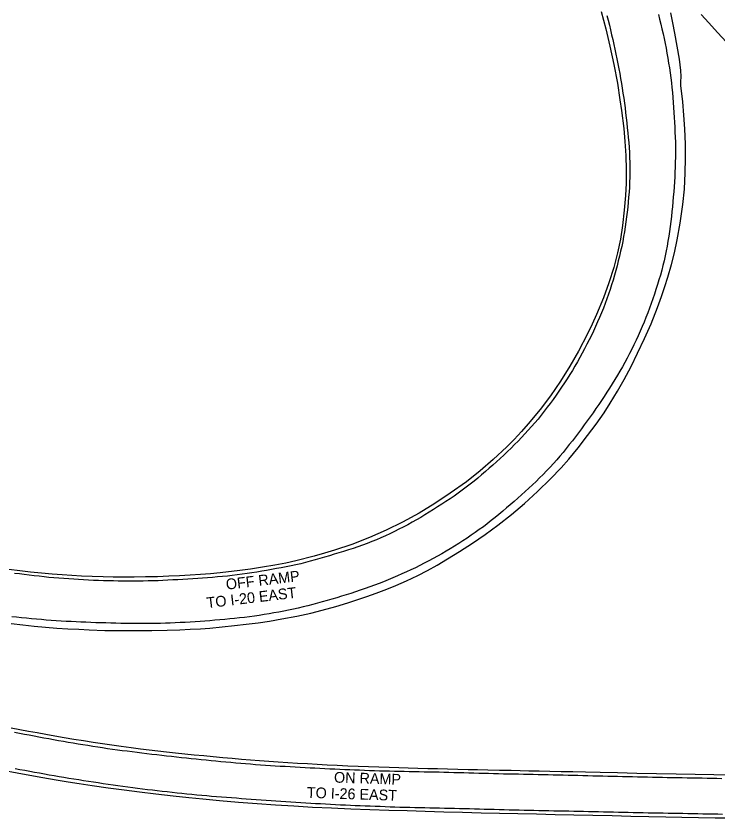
# Model space of a CAD drawing. Extents: x 1948091 to 1975253, y 787267 to 823306.
# Drawn here: x 1966364.3 to 1966717.4, y 800935.2 to 801338.4 of the extents above; entities that cross this region are included whole.
import ezdxf

# ---------------------------------------------------------------- set-up
doc = ezdxf.new("R2010")
doc.units = 0
for name, color, linetype in [('RD_EX_Pavement_Markings', 7, 'Continuous'), ('RD_EX_Road', 7, 'Continuous'), ('RD_TX_RoadID', 7, 'Continuous')]:
    doc.layers.add(name, color=color, linetype=linetype)

msp = doc.modelspace()

# ---------------------------------------------------------------- linework, layer by layer
at = {"layer": 'RD_EX_Pavement_Markings'}
for points in [[(1966687.48, 801339.26), (1966688.08, 801336.83), (1966688.68, 801334.41), (1966689.25, 801331.97), (1966689.82, 801329.54), (1966690.35, 801327.1), (1966690.85, 801324.65), (1966691.34, 801322.2), (1966691.77, 801319.73), (1966692.21, 801317.27), (1966692.61, 801314.8), (1966692.99, 801312.33), (1966693.35, 801309.86), (1966693.67, 801307.38), (1966693.97, 801304.9), (1966694.22, 801302.41), (1966694.47, 801299.93), (1966694.68, 801297.44), (1966694.9, 801294.95), (1966695.07, 801292.45), (1966695.25, 801289.96), (1966695.4, 801287.46), (1966695.55, 801284.97), (1966695.69, 801282.47), (1966695.8, 801279.98), (1966695.91, 801277.48), (1966695.98, 801274.98), (1966696, 801272.48), (1966696.01, 801269.98), (1966695.99, 801267.48), (1966695.95, 801264.98), (1966695.87, 801262.49), (1966695.8, 801259.99), (1966695.67, 801257.49), (1966695.54, 801255), (1966695.36, 801252.5), (1966695.16, 801250.01), (1966694.96, 801247.52), (1966694.73, 801245.03), (1966694.51, 801242.54), (1966694.26, 801240.06), (1966694, 801237.57), (1966693.73, 801235.09), (1966693.38, 801232.61), (1966693.03, 801230.14), (1966692.64, 801227.67), (1966692.24, 801225.2), (1966691.81, 801222.74), (1966691.37, 801220.28), (1966690.87, 801217.83), (1966690.33, 801215.39), (1966689.73, 801212.96), (1966689.1, 801210.55), (1966688.43, 801208.14), (1966687.71, 801205.75), (1966686.99, 801203.35), (1966686.24, 801200.97), (1966685.49, 801198.59), (1966684.68, 801196.22), (1966683.84, 801193.87), (1966682.96, 801191.53), (1966682.07, 801189.2), (1966681.16, 801186.87), (1966680.24, 801184.55), (1966679.26, 801182.25), (1966678.27, 801179.95), (1966677.26, 801177.67), (1966676.23, 801175.39), (1966675.15, 801173.14), (1966674.07, 801170.89), (1966672.93, 801168.67), (1966671.78, 801166.45), (1966670.58, 801164.25), (1966669.36, 801162.08), (1966668.12, 801159.91), (1966666.84, 801157.76), (1966665.56, 801155.62), (1966664.27, 801153.48), (1966662.93, 801151.37), (1966661.58, 801149.27), (1966660.2, 801147.18), (1966658.81, 801145.11), (1966657.43, 801143.03), (1966656.01, 801140.98), (1966654.58, 801138.93), (1966653.14, 801136.88), (1966651.67, 801134.86), (1966650.19, 801132.85), (1966648.71, 801130.84), (1966647.2, 801128.85), (1966645.69, 801126.86), (1966644.18, 801124.87), (1966642.64, 801122.9), (1966641.11, 801120.93), (1966639.53, 801119), (1966637.92, 801117.09), (1966636.28, 801115.2), (1966634.62, 801113.34), (1966632.94, 801111.49), (1966631.22, 801109.68), (1966629.48, 801107.89), (1966627.71, 801106.12), (1966625.94, 801104.36), (1966624.11, 801102.66), (1966622.28, 801100.96), (1966620.44, 801099.27), (1966618.58, 801097.6), (1966616.7, 801095.96), (1966614.82, 801094.31), (1966612.93, 801092.68), (1966611.03, 801091.06), (1966609.14, 801089.43), (1966607.22, 801087.83), (1966605.29, 801086.24), (1966603.35, 801084.67), (1966601.37, 801083.14), (1966599.4, 801081.62), (1966597.37, 801080.16), (1966595.32, 801078.72), (1966593.26, 801077.31), (1966591.2, 801075.9), (1966589.14, 801074.5), (1966587.02, 801073.17), (1966584.91, 801071.84), (1966582.77, 801070.54), (1966580.63, 801069.26), (1966578.48, 801067.99), (1966576.3, 801066.77), (1966574.12, 801065.55), (1966571.91, 801064.39), (1966569.7, 801063.24), (1966567.46, 801062.12), (1966565.22, 801061.01), (1966562.99, 801059.91), (1966560.71, 801058.88), (1966558.44, 801057.84), (1966556.15, 801056.84), (1966553.85, 801055.87), (1966551.55, 801054.9), (1966549.23, 801053.97), (1966546.91, 801053.05), (1966544.57, 801052.16), (1966542.22, 801051.32), (1966539.87, 801050.47), (1966537.51, 801049.66), (1966535.15, 801048.86), (1966532.78, 801048.06), (1966530.39, 801047.32), (1966528, 801046.61), (1966525.61, 801045.9), (1966523.21, 801045.21), (1966520.8, 801044.54), (1966518.39, 801043.87), (1966515.98, 801043.21), (1966513.57, 801042.56), (1966511.16, 801041.91), (1966508.74, 801041.29), (1966506.31, 801040.73), (1966503.87, 801040.18), (1966501.43, 801039.67), (1966498.98, 801039.19), (1966496.53, 801038.72), (1966494.07, 801038.27), (1966491.61, 801037.82), (1966489.15, 801037.43), (1966486.68, 801037.05), (1966484.21, 801036.69), (1966481.73, 801036.36), (1966479.26, 801036.03), (1966476.77, 801035.75), (1966474.29, 801035.48), (1966471.81, 801035.21), (1966469.32, 801034.99), (1966466.83, 801034.77), (1966464.35, 801034.54), (1966461.86, 801034.36), (1966459.36, 801034.18), (1966456.87, 801034.01), (1966454.38, 801033.83), (1966451.89, 801033.68), (1966449.4, 801033.53), (1966446.9, 801033.39), (1966444.41, 801033.28), (1966441.91, 801033.18), (1966439.42, 801033.08), (1966436.92, 801033.02), (1966434.43, 801032.98), (1966431.93, 801032.93), (1966429.43, 801032.9), (1966426.93, 801032.9), (1966424.44, 801032.9), (1966421.94, 801032.92), (1966419.44, 801032.97), (1966416.95, 801033.01), (1966414.45, 801033.07), (1966411.95, 801033.13), (1966409.46, 801033.2), (1966406.96, 801033.26), (1966404.47, 801033.34), (1966401.97, 801033.44), (1966399.48, 801033.54), (1966396.98, 801033.65), (1966394.48, 801033.75), (1966391.99, 801033.89), (1966389.5, 801034.03), (1966387.01, 801034.16), (1966384.51, 801034.3), (1966382.02, 801034.48), (1966379.53, 801034.69), (1966377.04, 801034.89), (1966374.55, 801035.09), (1966372.07, 801035.32), (1966369.58, 801035.55), (1966367.09, 801035.81), (1966364.61, 801036.07), (1966362.13, 801036.33)], [(1966661.44, 801338.73), (1966662.11, 801336.32), (1966662.77, 801333.91), (1966663.35, 801331.48), (1966663.94, 801329.05), (1966664.52, 801326.62), (1966665.05, 801324.18), (1966665.57, 801321.73), (1966666.08, 801319.29), (1966666.59, 801316.84), (1966667.06, 801314.38), (1966667.52, 801311.93), (1966667.99, 801309.47), (1966668.45, 801307.02), (1966668.85, 801304.55), (1966669.24, 801302.08), (1966669.63, 801299.61), (1966670.02, 801297.14), (1966670.35, 801294.67), (1966670.68, 801292.19), (1966670.98, 801289.71), (1966671.25, 801287.22), (1966671.51, 801284.74), (1966671.78, 801282.25), (1966672.04, 801279.77), (1966672.28, 801277.28), (1966672.5, 801274.79), (1966672.7, 801272.3), (1966672.85, 801269.8), (1966672.97, 801267.31), (1966673.02, 801264.81), (1966673.07, 801262.31), (1966673.05, 801259.81), (1966673.04, 801257.31), (1966672.95, 801254.81), (1966672.84, 801252.32), (1966672.69, 801249.82), (1966672.49, 801247.33), (1966672.3, 801244.84), (1966672.06, 801242.35), (1966671.79, 801239.87), (1966671.46, 801237.39), (1966671.12, 801234.91), (1966670.74, 801232.44), (1966670.33, 801229.98), (1966669.91, 801227.52), (1966669.49, 801225.05), (1966668.98, 801222.61), (1966668.46, 801220.16), (1966667.9, 801217.73), (1966667.29, 801215.3), (1966666.68, 801212.88), (1966666.03, 801210.47), (1966665.34, 801208.07), (1966664.64, 801205.67), (1966663.89, 801203.29), (1966663.13, 801200.91), (1966662.37, 801198.53), (1966661.52, 801196.17), (1966660.67, 801193.83), (1966659.77, 801191.5), (1966658.85, 801189.18), (1966657.88, 801186.88), (1966656.89, 801184.58), (1966655.87, 801182.3), (1966654.82, 801180.03), (1966653.72, 801177.79), (1966652.58, 801175.57), (1966651.43, 801173.35), (1966650.26, 801171.14), (1966649.09, 801168.94), (1966647.92, 801166.73), (1966646.69, 801164.55), (1966645.45, 801162.39), (1966644.16, 801160.25), (1966642.84, 801158.13), (1966641.51, 801156.02), (1966640.15, 801153.92), (1966638.79, 801151.83), (1966637.4, 801149.75), (1966635.98, 801147.7), (1966634.56, 801145.65), (1966633.05, 801143.65), (1966631.55, 801141.66), (1966630.04, 801139.67), (1966628.49, 801137.71), (1966626.91, 801135.77), (1966625.31, 801133.86), (1966623.65, 801131.99), (1966621.98, 801130.13), (1966620.27, 801128.31), (1966618.56, 801126.49), (1966616.83, 801124.69), (1966615.09, 801122.9), (1966613.33, 801121.13), (1966611.53, 801119.4), (1966609.73, 801117.67), (1966607.89, 801115.99), (1966606.04, 801114.3), (1966604.18, 801112.64), (1966602.3, 801111), (1966600.42, 801109.36), (1966598.54, 801107.71), (1966596.67, 801106.05), (1966594.72, 801104.5), (1966592.75, 801102.96), (1966590.77, 801101.45), (1966588.76, 801099.96), (1966586.75, 801098.48), (1966584.7, 801097.05), (1966582.64, 801095.64), (1966580.58, 801094.23), (1966578.48, 801092.88), (1966576.38, 801091.53), (1966574.27, 801090.19), (1966572.14, 801088.89), (1966570.01, 801087.59), (1966567.87, 801086.29), (1966565.69, 801085.07), (1966563.52, 801083.84), (1966561.33, 801082.64), (1966559.12, 801081.46), (1966556.91, 801080.3), (1966554.68, 801079.18), (1966552.43, 801078.09), (1966550.15, 801077.08), (1966547.87, 801076.06), (1966545.57, 801075.08), (1966543.27, 801074.1), (1966540.95, 801073.19), (1966538.61, 801072.32), (1966536.25, 801071.48), (1966533.88, 801070.7), (1966531.5, 801069.94), (1966529.12, 801069.21), (1966526.73, 801068.48), (1966524.34, 801067.75), (1966521.95, 801067.03), (1966519.56, 801066.31), (1966517.16, 801065.62), (1966514.76, 801064.94), (1966512.35, 801064.26), (1966509.94, 801063.64), (1966507.51, 801063.03), (1966505.09, 801062.45), (1966502.64, 801061.94), (1966500.2, 801061.44), (1966497.74, 801060.98), (1966495.29, 801060.52), (1966492.84, 801060.06), (1966490.38, 801059.6), (1966487.92, 801059.2), (1966485.45, 801058.81), (1966482.99, 801058.42), (1966480.52, 801058.06), (1966478.04, 801057.73), (1966475.57, 801057.41), (1966473.09, 801057.08), (1966470.61, 801056.78), (1966468.13, 801056.55), (1966465.64, 801056.33), (1966463.16, 801056.1), (1966460.67, 801055.91), (1966458.18, 801055.73), (1966455.69, 801055.56), (1966453.2, 801055.39), (1966450.71, 801055.21), (1966448.21, 801055.08), (1966445.72, 801054.95), (1966443.23, 801054.82), (1966440.73, 801054.68), (1966438.24, 801054.56), (1966435.74, 801054.48), (1966433.25, 801054.4), (1966430.75, 801054.32), (1966428.26, 801054.24), (1966425.76, 801054.19), (1966423.26, 801054.21), (1966420.76, 801054.24), (1966418.27, 801054.26), (1966415.77, 801054.28), (1966413.27, 801054.34), (1966410.78, 801054.41), (1966408.28, 801054.47), (1966405.79, 801054.54), (1966403.29, 801054.64), (1966400.8, 801054.77), (1966398.3, 801054.89), (1966395.81, 801055.02), (1966393.32, 801055.18), (1966390.83, 801055.36), (1966388.34, 801055.54), (1966385.85, 801055.72), (1966383.35, 801055.9), (1966380.87, 801056.16), (1966378.39, 801056.42), (1966375.9, 801056.68), (1966373.42, 801056.95), (1966370.94, 801057.24), (1966368.46, 801057.54), (1966365.98, 801057.84), (1966363.5, 801058.14)], [(1966363.59, 800978.29), (1966366.05, 800977.82), (1966368.5, 800977.35), (1966370.95, 800976.89), (1966373.41, 800976.42), (1966375.86, 800975.97), (1966378.32, 800975.52), (1966380.77, 800975.07), (1966383.23, 800974.62), (1966385.68, 800974.17), (1966388.14, 800973.74), (1966390.61, 800973.33), (1966393.07, 800972.92), (1966395.53, 800972.5), (1966397.99, 800972.09), (1966400.46, 800971.69), (1966402.92, 800971.3), (1966405.39, 800970.91), (1966407.85, 800970.52), (1966410.33, 800970.17), (1966412.8, 800969.82), (1966415.27, 800969.48), (1966417.75, 800969.15), (1966420.22, 800968.83), (1966422.7, 800968.5), (1966425.17, 800968.18), (1966427.65, 800967.88), (1966430.13, 800967.6), (1966432.62, 800967.32), (1966435.1, 800967.03), (1966437.58, 800966.75), (1966440.06, 800966.47), (1966442.54, 800966.19), (1966445.02, 800965.92), (1966447.5, 800965.64), (1966449.98, 800965.37), (1966452.47, 800965.09), (1966454.95, 800964.85), (1966457.44, 800964.6), (1966459.92, 800964.35), (1966462.4, 800964.11), (1966464.89, 800963.86), (1966467.38, 800963.62), (1966469.86, 800963.39), (1966472.35, 800963.16), (1966474.83, 800962.93), (1966477.32, 800962.72), (1966479.81, 800962.52), (1966482.3, 800962.32), (1966484.79, 800962.12), (1966487.28, 800961.93), (1966489.77, 800961.77), (1966492.26, 800961.61), (1966494.75, 800961.44), (1966497.25, 800961.28), (1966499.74, 800961.12), (1966502.23, 800960.98), (1966504.72, 800960.85), (1966507.22, 800960.71), (1966509.71, 800960.57), (1966512.2, 800960.43), (1966514.7, 800960.29), (1966517.19, 800960.17), (1966519.68, 800960.05), (1966522.18, 800959.94), (1966524.67, 800959.82), (1966527.17, 800959.7), (1966529.66, 800959.58), (1966532.16, 800959.47), (1966534.65, 800959.38), (1966537.15, 800959.28), (1966539.64, 800959.19), (1966542.14, 800959.1), (1966544.63, 800959), (1966547.13, 800958.93), (1966549.63, 800958.87), (1966552.12, 800958.81), (1966554.62, 800958.75), (1966557.12, 800958.69), (1966559.61, 800958.63), (1966562.11, 800958.58), (1966564.6, 800958.53), (1966567.1, 800958.48), (1966569.6, 800958.42), (1966572.1, 800958.37), (1966574.59, 800958.32), (1966577.09, 800958.27), (1966579.59, 800958.22), (1966582.08, 800958.17), (1966584.58, 800958.1), (1966587.07, 800958.03), (1966589.57, 800957.96), (1966592.07, 800957.89), (1966594.56, 800957.83), (1966597.06, 800957.76), (1966599.56, 800957.69), (1966602.05, 800957.62), (1966604.55, 800957.55), (1966607.05, 800957.49), (1966609.54, 800957.43), (1966612.04, 800957.38), (1966614.53, 800957.33), (1966617.03, 800957.27), (1966619.53, 800957.22), (1966622.02, 800957.16), (1966624.52, 800957.11), (1966627.02, 800957.05), (1966629.51, 800957), (1966632.01, 800956.94), (1966634.51, 800956.89), (1966637, 800956.83), (1966639.5, 800956.77), (1966642, 800956.71), (1966644.49, 800956.65), (1966646.99, 800956.6), (1966649.49, 800956.54), (1966651.98, 800956.48), (1966654.48, 800956.42), (1966656.98, 800956.36), (1966659.47, 800956.31), (1966661.97, 800956.25), (1966664.47, 800956.19), (1966666.96, 800956.13), (1966669.46, 800956.07), (1966671.96, 800956.01), (1966674.45, 800955.95), (1966676.95, 800955.89), (1966679.45, 800955.83), (1966681.94, 800955.77), (1966684.44, 800955.71), (1966686.94, 800955.66), (1966689.44, 800955.62), (1966691.93, 800955.57), (1966694.43, 800955.53), (1966696.93, 800955.49), (1966699.43, 800955.44), (1966701.93, 800955.4), (1966704.42, 800955.35), (1966706.92, 800955.31), (1966709.42, 800955.26), (1966711.92, 800955.21), (1966714.41, 800955.16), (1966716.91, 800955.11), (1966719.41, 800955.06)], [(1966719.78, 800936.96), (1966717.28, 800937), (1966714.78, 800937.05), (1966712.28, 800937.09), (1966709.78, 800937.14), (1966707.28, 800937.18), (1966704.78, 800937.23), (1966702.29, 800937.27), (1966699.79, 800937.32), (1966697.29, 800937.36), (1966694.79, 800937.41), (1966692.29, 800937.45), (1966689.79, 800937.5), (1966687.29, 800937.54), (1966684.79, 800937.59), (1966682.3, 800937.64), (1966679.8, 800937.68), (1966677.3, 800937.73), (1966674.8, 800937.79), (1966672.3, 800937.85), (1966669.81, 800937.91), (1966667.31, 800937.97), (1966664.81, 800938.03), (1966662.31, 800938.09), (1966659.81, 800938.15), (1966657.32, 800938.21), (1966654.82, 800938.27), (1966652.32, 800938.32), (1966649.82, 800938.37), (1966647.32, 800938.41), (1966644.83, 800938.45), (1966642.33, 800938.5), (1966639.83, 800938.54), (1966637.33, 800938.59), (1966634.84, 800938.63), (1966632.34, 800938.67), (1966629.84, 800938.72), (1966627.34, 800938.77), (1966624.85, 800938.83), (1966622.35, 800938.89), (1966619.85, 800938.96), (1966617.35, 800939.02), (1966614.86, 800939.08), (1966612.36, 800939.15), (1966609.86, 800939.21), (1966607.37, 800939.27), (1966604.87, 800939.34), (1966602.37, 800939.4), (1966599.88, 800939.47), (1966597.38, 800939.54), (1966594.88, 800939.6), (1966592.39, 800939.67), (1966589.89, 800939.73), (1966587.39, 800939.79), (1966584.9, 800939.85), (1966582.4, 800939.91), (1966579.9, 800939.97), (1966577.41, 800940.03), (1966574.91, 800940.09), (1966572.41, 800940.15), (1966569.92, 800940.2), (1966567.42, 800940.25), (1966564.92, 800940.31), (1966562.42, 800940.36), (1966559.93, 800940.41), (1966557.43, 800940.48), (1966554.93, 800940.57), (1966552.44, 800940.66), (1966549.94, 800940.75), (1966547.45, 800940.84), (1966544.95, 800940.93), (1966542.46, 800941.03), (1966539.96, 800941.13), (1966537.47, 800941.23), (1966534.97, 800941.33), (1966532.48, 800941.42), (1966529.98, 800941.55), (1966527.49, 800941.67), (1966524.99, 800941.8), (1966522.5, 800941.92), (1966520.01, 800942.05), (1966517.51, 800942.18), (1966515.02, 800942.33), (1966512.53, 800942.48), (1966510.03, 800942.62), (1966507.54, 800942.77), (1966505.05, 800942.92), (1966502.56, 800943.08), (1966500.07, 800943.25), (1966497.58, 800943.42), (1966495.08, 800943.59), (1966492.59, 800943.76), (1966490.1, 800943.93), (1966487.61, 800944.11), (1966485.12, 800944.29), (1966482.63, 800944.47), (1966480.14, 800944.65), (1966477.65, 800944.84), (1966475.16, 800945.03), (1966472.67, 800945.22), (1966470.18, 800945.41), (1966467.69, 800945.6), (1966465.2, 800945.81), (1966462.71, 800946.03), (1966460.23, 800946.25), (1966457.74, 800946.47), (1966455.25, 800946.7), (1966452.77, 800946.95), (1966450.28, 800947.19), (1966447.8, 800947.44), (1966445.31, 800947.69), (1966442.83, 800947.96), (1966440.35, 800948.23), (1966437.87, 800948.5), (1966435.38, 800948.77), (1966432.91, 800949.07), (1966430.43, 800949.38), (1966427.95, 800949.69), (1966425.47, 800950), (1966423, 800950.33), (1966420.53, 800950.67), (1966418.05, 800951.01), (1966415.58, 800951.35), (1966413.11, 800951.7), (1966410.63, 800952.05), (1966408.16, 800952.4), (1966405.69, 800952.76), (1966403.22, 800953.12), (1966400.75, 800953.5), (1966398.29, 800953.88), (1966395.82, 800954.27), (1966393.35, 800954.65), (1966390.89, 800955.05), (1966388.43, 800955.47), (1966385.97, 800955.9), (1966383.51, 800956.33), (1966381.05, 800956.75), (1966378.59, 800957.19), (1966376.13, 800957.62), (1966373.67, 800958.06), (1966371.21, 800958.49), (1966368.75, 800958.94), (1966366.3, 800959.39), (1966363.84, 800959.84)]]:
    msp.add_lwpolyline(points, dxfattribs=at)
at = {"layer": 'RD_EX_Road'}
for points in [[(1966658.7, 801340.76), (1966661.04, 801332.06), (1966663.07, 801323.26), (1966665.04, 801314.13), (1966666.87, 801304.64), (1966668.12, 801296.36), (1966668.84, 801290.94), (1966669.98, 801281.89), (1966670.62, 801275.35), (1966671.05, 801268.22), (1966671.25, 801261.06), (1966671.2, 801254.31), (1966670.87, 801248.17), (1966670.22, 801240.85), (1966669.35, 801233.09), (1966668.32, 801226.29), (1966666.91, 801219.37), (1966665.03, 801212.04), (1966662.59, 801204.28), (1966659.82, 801196.76), (1966656.35, 801188.32), (1966654.19, 801183.47), (1966651.84, 801178.6), (1966647.23, 801169.85), (1966642.84, 801162.28), (1966638.21, 801154.8), (1966633.24, 801147.4), (1966628.03, 801140.53), (1966622.01, 801133.36), (1966618.53, 801129.44), (1966614.86, 801125.53), (1966611.18, 801121.81), (1966604.25, 801115.36), (1966597.71, 801109.67), (1966590.86, 801104.21), (1966582.76, 801098.42), (1966575.03, 801093.24), (1966567.07, 801088.38), (1966558.74, 801083.83), (1966550.56, 801079.83), (1966542.13, 801076.17), (1966533.18, 801072.69), (1966524.49, 801069.84), (1966519.46, 801068.3), (1966514.36, 801066.81), (1966505.07, 801064.41), (1966500.02, 801063.33), (1966494.47, 801062.28), (1966488.35, 801061.22), (1966482.28, 801060.27), (1966476.89, 801059.53), (1966467.04, 801058.43), (1966462.15, 801057.97), (1966457.05, 801057.56), (1966451.84, 801057.2), (1966446.62, 801056.91), (1966441.2, 801056.67), (1966435.4, 801056.49), (1966429.5, 801056.36), (1966423.77, 801056.3), (1966418.3, 801056.3), (1966413.19, 801056.32), (1966408.09, 801056.41), (1966402.63, 801056.56), (1966397.25, 801056.77), (1966387.53, 801057.37), (1966382.46, 801057.76), (1966377.16, 801058.23), (1966371.67, 801058.81), (1966366.15, 801059.46), (1966360.73, 801060.15)], [(1966361.89, 801032.9), (1966367.69, 801032.2), (1966373.44, 801031.59), (1966379.11, 801031.09), (1966384.76, 801030.68), (1966390.39, 801030.34), (1966395.85, 801030.02), (1966401.02, 801029.72), (1966408.98, 801029.44), (1966417.45, 801029.37), (1966424, 801029.37), (1966432.57, 801029.45), (1966440.39, 801029.56), (1966446.77, 801029.79), (1966451.93, 801030.09), (1966457.14, 801030.32), (1966461.78, 801030.65), (1966467.93, 801031.24), (1966474.13, 801031.88), (1966480.02, 801032.55), (1966486.12, 801033.33), (1966491.74, 801034.17), (1966498.03, 801035.27), (1966505.5, 801036.7), (1966512.58, 801038.21), (1966518.26, 801039.57), (1966525.11, 801041.44), (1966531.2, 801043.32), (1966535.8, 801044.82), (1966540.8, 801046.5), (1966545.53, 801048.13), (1966550.79, 801050.14), (1966555.33, 801052.03), (1966560.74, 801054.47), (1966566.36, 801057.15), (1966571.28, 801059.66), (1966576.2, 801062.34), (1966581.44, 801065.42), (1966587.47, 801069.2), (1966593.9, 801073.36), (1966600.26, 801077.68), (1966606.73, 801082.37), (1966613.55, 801087.7), (1966620.16, 801093.36), (1966626.7, 801099.37), (1966633.21, 801105.72), (1966638.53, 801111.24), (1966642.39, 801115.51), (1966647.01, 801121.27), (1966651.76, 801127.51), (1966656.07, 801133.26), (1966660.1, 801138.92), (1966663.21, 801143.7), (1966666.87, 801149.8), (1966670.23, 801155.7), (1966673.71, 801162.26), (1966676.95, 801168.83), (1966680.49, 801176.3), (1966683.74, 801183.57), (1966687.02, 801191.88), (1966689.06, 801197.45), (1966690.75, 801202.34), (1966692.27, 801207.18), (1966694.04, 801213.41), (1966695.54, 801219.34), (1966696.93, 801225.85), (1966698.42, 801234.18), (1966699.69, 801243.67), (1966700.52, 801251.43), (1966700.99, 801259.57), (1966701.16, 801266.82), (1966701.11, 801273.97), (1966700.79, 801281.62), (1966700.31, 801288.53), (1966699.68, 801295.24), (1966699.06, 801300.76), (1966698.78, 801303.34), (1966698.8, 801305.26), (1966698.85, 801308.02), (1966698.73, 801311.06), (1966698, 801316.71), (1966696.95, 801323.26), (1966695.68, 801329.83), (1966694.65, 801334.92), (1966693.66, 801339.95)], [(1966708.91, 801339.23), (1966712.77, 801335.03), (1966717.19, 801330.2), (1966721.66, 801325.31)], [(1966361.88, 800980.54), (1966366.22, 800979.69), (1966370.56, 800978.87), (1966374.89, 800978.05), (1966379.29, 800977.24), (1966383.86, 800976.44), (1966388.58, 800975.64), (1966393.45, 800974.85), (1966398.33, 800974.07), (1966403.07, 800973.33), (1966407.76, 800972.63), (1966412.46, 800971.94), (1966417.24, 800971.27), (1966422.16, 800970.6), (1966426.94, 800969.96), (1966431.32, 800969.42), (1966435.59, 800968.92), (1966440, 800968.44), (1966444.56, 800967.95), (1966449.24, 800967.46), (1966453.99, 800966.97), (1966458.77, 800966.5), (1966463.56, 800966.06), (1966468.34, 800965.62), (1966473.06, 800965.19), (1966477.66, 800964.8), (1966482.21, 800964.43), (1966486.79, 800964.09), (1966491.43, 800963.75), (1966496.2, 800963.4), (1966501.04, 800963.06), (1966505.93, 800962.75), (1966510.85, 800962.48), (1966515.79, 800962.21), (1966520.8, 800961.94), (1966525.94, 800961.67), (1966531.15, 800961.41), (1966536.38, 800961.19), (1966541.63, 800961), (1966546.88, 800960.81), (1966551.99, 800960.63), (1966556.81, 800960.48), (1966561.56, 800960.34), (1966566.46, 800960.21), (1966571.42, 800960.07), (1966576.38, 800959.95), (1966581.42, 800959.83), (1966586.6, 800959.71), (1966591.7, 800959.6), (1966596.51, 800959.5), (1966601.6, 800959.39), (1966607.53, 800959.27), (1966613.31, 800959.13), (1966617.92, 800959.02), (1966622.29, 800958.91), (1966627.39, 800958.8), (1966632.91, 800958.69), (1966638.57, 800958.57), (1966644.49, 800958.45), (1966650.81, 800958.31), (1966658.11, 800958.15), (1966666.92, 800957.95), (1966676.61, 800957.73), (1966686.55, 800957.53), (1966696.45, 800957.33), (1966706.03, 800957.15), (1966715.42, 800956.97), (1966724.75, 800956.8)], [(1966357.73, 800959.25), (1966364.84, 800957.89), (1966371.17, 800956.73), (1966377.75, 800955.57), (1966384.58, 800954.39), (1966390.62, 800953.38), (1966396.02, 800952.5), (1966402.68, 800951.49), (1966410.68, 800950.33), (1966418.63, 800949.24), (1966426.42, 800948.24), (1966434.72, 800947.25), (1966443.44, 800946.29), (1966451.27, 800945.47), (1966458.34, 800944.78), (1966466.61, 800944.01), (1966476.19, 800943.16), (1966485.64, 800942.41), (1966494.79, 800941.78), (1966504.05, 800941.2), (1966513.48, 800940.66), (1966523.06, 800940.17), (1966532.75, 800939.74), (1966542.34, 800939.39), (1966551.78, 800939.1), (1966561.03, 800938.83), (1966570.14, 800938.56), (1966579.44, 800938.29), (1966588.94, 800938.03), (1966598.3, 800937.79), (1966607.49, 800937.59), (1966616.75, 800937.39), (1966626.1, 800937.17), (1966635.46, 800936.96), (1966644.85, 800936.75), (1966654.43, 800936.54), (1966664.15, 800936.34), (1966673.58, 800936.14), (1966682.63, 800935.95), (1966691.16, 800935.76), (1966699.25, 800935.58), (1966707.6, 800935.42), (1966716.04, 800935.28), (1966722.82, 800935.16)]]:
    msp.add_lwpolyline(points, dxfattribs=at)

# ---------------------------------------------------------------- texts
at = {"layer": 'RD_TX_RoadID'}
for s, rotation, p in [('OFF RAMP', 6.6982, (1966470.2, 801049.92)), ('TO I-20 EAST', 6.6982, (1966460.5, 801040.63)), ('ON RAMP', 358.0882, (1966524.2, 800952.96)), ('TO I-26 EAST', 358.0882, (1966510.54, 800945.31))]:
    msp.add_text(s, height=5.4, rotation=rotation, dxfattribs=at).set_placement(p)

doc.saveas('drawing.dxf')
